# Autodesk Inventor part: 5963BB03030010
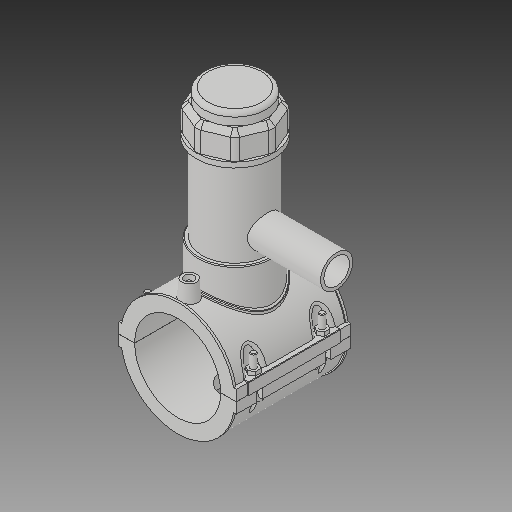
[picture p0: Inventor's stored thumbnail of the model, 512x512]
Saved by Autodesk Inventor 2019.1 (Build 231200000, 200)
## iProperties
Created: 2017-07
Part Number: 5963BB03030010
Material: Generic
Description: PLASSON TAPPING SADDLE 3''IPS x 1''IPS
Document SubType Name: Modeling
Designer: KIM
Mass: 1712.7 g
Surface Area: 2671.49 cm^2
Volume: 1712.7 cm^3
Density: 1 g/cm^3
Appearance: Default
Author: KIM
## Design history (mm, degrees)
derived "5963B.ipt"
feature "Solid1::5963B.ipt"
feature "Solid2::5963B.ipt"
feature "Solid4::5963B.ipt"
feature "Solid5::5963B.ipt"
tag "TaggingFeature1"
body "Solid1"
body "Solid2"
other parameters: "d0" = 88.7, "d2" = 120.904, "d3" = 22.175, "d4" = 118.11, "d5" = 0, "d6" = 0.1, "d8" = 0, "d19" = 6, "d20" = 6, "d21" = 70.866, "d23" = 0, "d24" = 35.433, "d26" = 0, "d29" = 3, "d30" = 29.56667, "d31" = 6, "d32" = 0, "d33" = 0, "d34" = 0.6, "d40" = 59.9612, "d41" = 79.83, "d43" = 0, "d45" = 0, "d47" = 128.521, "d70" = 15, "d72" = 0, "d73" = 6, "d75" = 5, "d76" = 0, "d77" = 4.435, "d78" = 74.35, "d79" = 15, "d80" = 47.244, "d82" = 5 deg, "d84" = 4, "d85" = 14, "d86" = 0, "d87" = 3, "d88" = 0, "d89" = 1, "d90" = 1, "d91" = 94.488, "d92" = 0, "d93" = 0.5, "d94" = 46.68421, "d96" = 117.6162, "d97" = 2.3622, "d98" = 0, "d102" = 0.887, "d120" = 140 deg, "d121" = 24.228, "d122" = 20 deg, "d123" = 230.62, "d124" = 69.186, "d126" = 0, "d143" = 91.361, "d145" = 20.46923, "d149" = 1.3305, "d150" = 22.51615, "d153" = 118.11, "d154" = 0, "d156" = 57.655, "d157" = 160 deg, "d159" = 5.322, "d161" = 1.3305, "d162" = 70.866, "d163" = 0, "d164" = 44.35, "d167" = 8.87, "d168" = 56.24878, "d170" = 3.2805, "d172" = 0, "d173" = 1, "d175" = 44.35, "d176" = 20 deg, "d177" = 6.209, "d178" = 26.61, "d180" = 0, "d183" = 10.644, "d184" = 4.9672, "d185" = 38.38575, "d186" = 38.38575, "d187" = 57.655, "d188" = 7.983, "d189" = 6.209, "d190" = 0, "d191" = 86.4825, "d193" = 6.1236, "d194" = 4.13385, "d195" = 90 deg, "d197" = 0, "d199" = 0, "d200" = 13.305, "d202" = 0, "d203" = 177.038, "d204" = 75.8385, "d205" = 55.881, "d206" = 67.8555, "d207" = 132.7785, "d208" = 138.08964, "d209" = 164.64534, "d210" = 68.6538, "d211" = 79.83, "d212" = 63.864, "d213" = 43.5366, "d216" = 0, "d217" = 8.87, "d218" = 4.435, "d219" = 0.887, "d222" = 88.7, "d224" = 0, "d230" = 5.322, "d233" = 6, "d236" = 60.452, "d237" = 35.433, "d238" = 6.02433, "d240" = 35.433, "d241" = 35.433, "d242" = 35.433, "d243" = 6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
